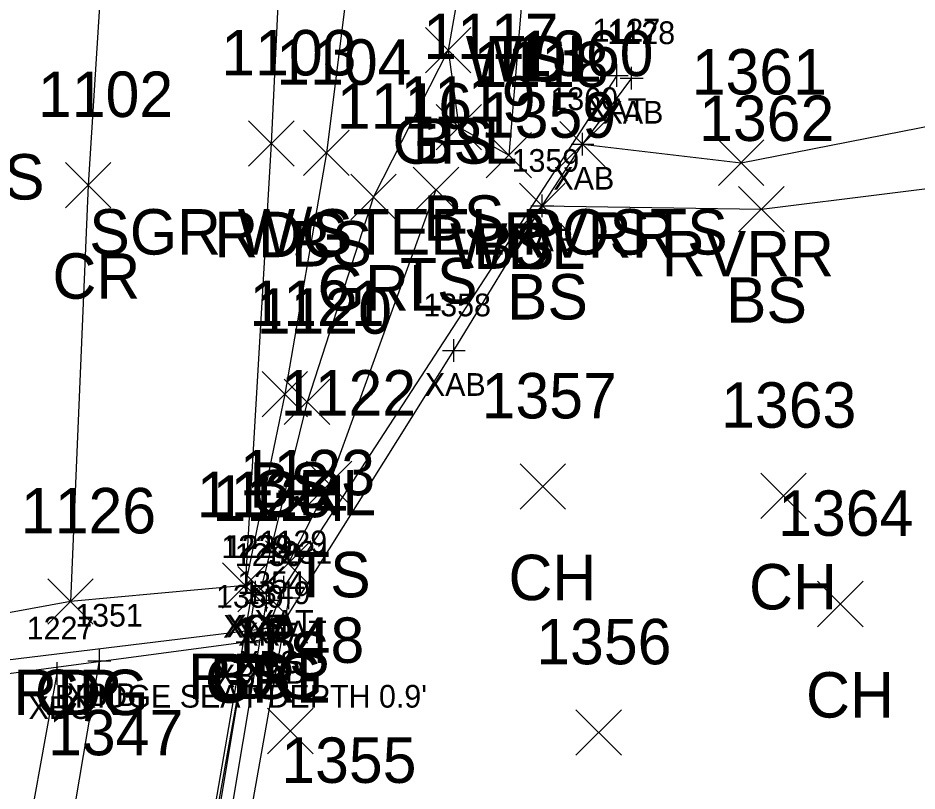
# Model space of a CAD drawing. Extents: x 1678553 to 1680768, y 787260 to 792325.
# Drawn here: x 1678697.83 to 1678737.39, y 787554.21 to 787588.24 of the extents above; entities that cross this region are included whole.
import ezdxf

# ---------------------------------------------------------------- set-up
doc = ezdxf.new("R2010")
doc.units = 0
for name, color, linetype in [('B_A', 7, 'Continuous'), ('B_C', 7, 'Continuous'), ('B_I', 7, 'Continuous'), ('B_TIC', 7, 'Continuous'), ('BB', 7, 'Continuous'), ('BDC', 7, 'Continuous'), ('BELB', 7, 'Continuous'), ('BF', 7, 'Continuous'), ('BR', 7, 'Continuous'), ('BSE', 7, 'Continuous'), ('BSUBM', 7, 'Continuous'), ('Default', 7, 'Continuous'), ('L_A', 7, 'Continuous'), ('L_I', 7, 'Continuous'), ('L_TIC', 7, 'Continuous'), ('LAWA', 7, 'Continuous'), ('LAWE', 7, 'Continuous'), ('LELB', 7, 'Continuous'), ('P_A', 7, 'Continuous'), ('P_I', 7, 'Continuous'), ('P_TIC', 7, 'Continuous'), ('PEU', 7, 'Continuous'), ('PRC', 7, 'Continuous'), ('R_A', 7, 'Continuous'), ('R_C', 7, 'Continuous'), ('R_I', 7, 'Continuous'), ('R_TIC', 7, 'Continuous'), ('RGR', 7, 'Continuous')]:
    doc.layers.add(name, color=color, linetype=linetype)

msp = doc.modelspace()

# ---------------------------------------------------------------- linework, layer by layer
at = {"layer": 'B_TIC'}
for p, q in [((1678724.175, 787585.703), (1678724.251, 787585.703)), ((1678724.834, 787585.589), (1678724.909, 787585.589)), ((1678722.672, 787582.686), (1678722.748, 787582.686)), ((1678722.672, 787582.686), (1678722.748, 787582.686)), ((1678720.903, 787579.967), (1678720.978, 787579.967)), ((1678717.015, 787573.607), (1678717.09, 787573.607)), ((1678709.532, 787563.18), (1678709.608, 787563.18)), ((1678708.126, 787562.968), (1678708.201, 787562.968)), ((1678708.286, 787562.971), (1678708.361, 787562.971)), ((1678708.763, 787562.617), (1678708.839, 787562.617)), ((1678709.747, 787562.716), (1678709.822, 787562.716)), ((1678708.828, 787561.383), (1678708.903, 787561.383)), ((1678709.077, 787560.939), (1678709.152, 787560.939)), ((1678707.935, 787560.782), (1678708.011, 787560.782)), ((1678701.415, 787559.95), (1678701.49, 787559.95)), ((1678699.566, 787559.385), (1678699.641, 787559.385))]:
    msp.add_line(p, q, dxfattribs=at)
for points in [[(1678724.172, 787585.203), (1678724.172, 787586.203)], [(1678724.83, 787585.089), (1678724.83, 787586.089)], [(1678723.672, 787585.703), (1678724.672, 787585.703)], [(1678724.33, 787585.589), (1678725.33, 787585.589)], [(1678722.669, 787582.186), (1678722.669, 787583.186)], [(1678722.669, 787582.186), (1678722.669, 787583.186)], [(1678722.169, 787582.686), (1678723.169, 787582.686)], [(1678722.169, 787582.686), (1678723.169, 787582.686)], [(1678720.9, 787579.467), (1678720.9, 787580.467)], [(1678720.4, 787579.967), (1678721.4, 787579.967)], [(1678717.011, 787573.107), (1678717.011, 787574.107)], [(1678716.511, 787573.607), (1678717.511, 787573.607)], [(1678709.529, 787562.68), (1678709.529, 787563.68)], [(1678708.123, 787562.468), (1678708.123, 787563.468)], [(1678708.282, 787562.471), (1678708.282, 787563.471)], [(1678709.029, 787563.18), (1678710.029, 787563.18)], [(1678709.743, 787562.216), (1678709.743, 787563.216)], [(1678707.623, 787562.968), (1678708.623, 787562.968)], [(1678707.782, 787562.971), (1678708.782, 787562.971)], [(1678708.76, 787562.117), (1678708.76, 787563.117)], [(1678708.26, 787562.617), (1678709.26, 787562.617)], [(1678709.243, 787562.716), (1678710.243, 787562.716)], [(1678708.824, 787560.883), (1678708.824, 787561.883)], [(1678707.932, 787560.282), (1678707.932, 787561.282)], [(1678708.324, 787561.383), (1678709.324, 787561.383)], [(1678709.073, 787560.439), (1678709.073, 787561.439)], [(1678708.573, 787560.939), (1678709.573, 787560.939)], [(1678701.411, 787559.45), (1678701.411, 787560.45)], [(1678707.432, 787560.782), (1678708.432, 787560.782)], [(1678699.562, 787558.885), (1678699.562, 787559.885)], [(1678700.911, 787559.95), (1678701.911, 787559.95)], [(1678699.062, 787559.385), (1678700.062, 787559.385)]]:
    msp.add_lwpolyline(points, dxfattribs=at)
at = {"layer": 'BB'}
for points in [[(1678701.803, 787526.419), (1678707.932, 787560.782)], [(1678695.571, 787525.394), (1678701.411, 787559.95)]]:
    msp.add_lwpolyline(points, dxfattribs=at)
at = {"layer": 'BDC'}
for points in [[(1678708.123, 787562.968), (1678704.887, 787544.249), (1678701.43, 787523.472)], [(1678708.282, 787562.971), (1678705.145, 787544.189), (1678701.582, 787523.722)]]:
    msp.add_lwpolyline(points, dxfattribs=at)
at = {"layer": 'BELB'}
msp.add_lwpolyline([(1678692.969, 787524.163), (1678696.171, 787540.725), (1678699.562, 787559.385)], dxfattribs=at)
at = {"layer": 'BF'}
msp.add_lwpolyline([(1678709.743, 787562.716), (1678706.422, 787543.978), (1678702.806, 787523.371)], dxfattribs=at)
at = {"layer": 'BR'}
msp.add_lwpolyline([(1678708.76, 787562.617), (1678705.642, 787543.945), (1678702.196, 787523.942)], dxfattribs=at)
at = {"layer": 'BSE'}
msp.add_lwpolyline([(1678689.043, 787558.968), (1678708.824, 787561.383)], dxfattribs=at)
at = {"layer": 'BSUBM'}
for points in [[(1678724.172, 787585.703), (1678709.529, 787563.18)], [(1678724.83, 787585.589), (1678722.669, 787582.686)], [(1678677.396, 787568.583), (1678684.574, 787562.134), (1678686.585, 787560.22), (1678689.048, 787558.274), (1678709.073, 787560.939), (1678717.011, 787573.607), (1678720.9, 787579.967), (1678722.669, 787582.686)]]:
    msp.add_lwpolyline(points, dxfattribs=at)
at = {"layer": 'Default'}
msp.add_line((1678709.529, 787563.18), (1678708.824, 787561.383), dxfattribs=at)
at = {"layer": 'L_TIC'}
for points in [[(1678715.762, 787585.825), (1678717.762, 787587.825)], [(1678717.762, 787585.825), (1678715.762, 787587.825)], [(1678716.223, 787582.431), (1678718.223, 787584.431)], [(1678718.223, 787582.431), (1678716.223, 787584.431)], [(1678721.669, 787581.686), (1678723.669, 787583.686)], [(1678723.669, 787581.686), (1678721.669, 787583.686)], [(1678710.399, 787581.3), (1678712.399, 787583.3)], [(1678712.399, 787581.3), (1678710.399, 787583.3)], [(1678718.428, 787581.197), (1678720.428, 787583.197)], [(1678720.428, 787581.197), (1678718.428, 787583.197)], [(1678718.428, 787581.197), (1678720.428, 787583.197)], [(1678720.428, 787581.197), (1678718.428, 787583.197)], [(1678728.644, 787580.87), (1678730.644, 787582.87)], [(1678730.644, 787580.87), (1678728.644, 787582.87)], [(1678715.221, 787579.674), (1678717.221, 787581.674)], [(1678717.221, 787579.674), (1678715.221, 787581.674)], [(1678719.9, 787578.967), (1678721.9, 787580.967)], [(1678721.9, 787578.967), (1678719.9, 787580.967)], [(1678729.536, 787578.825), (1678731.536, 787580.825)], [(1678731.536, 787578.825), (1678729.536, 787580.825)], [(1678708.575, 787570.681), (1678710.575, 787572.681)], [(1678710.575, 787570.681), (1678708.575, 787572.681)], [(1678710.522, 787566.739), (1678712.522, 787568.739)], [(1678712.522, 787566.739), (1678710.522, 787568.739)], [(1678719.923, 787566.613), (1678721.923, 787568.613)], [(1678721.923, 787566.613), (1678719.923, 787568.613)], [(1678730.507, 787566.204), (1678732.507, 787568.204)], [(1678732.507, 787566.204), (1678730.507, 787568.204)], [(1678708.718, 787563.23), (1678710.718, 787565.23)], [(1678710.718, 787563.23), (1678708.718, 787565.23)], [(1678706.824, 787562.264), (1678708.824, 787564.264)], [(1678708.824, 787562.264), (1678706.824, 787564.264)], [(1678733.014, 787561.445), (1678735.014, 787563.445)], [(1678735.014, 787561.445), (1678733.014, 787563.445)], [(1678708.811, 787555.853), (1678710.811, 787557.853)], [(1678710.811, 787555.853), (1678708.811, 787557.853)], [(1678722.379, 787555.79), (1678724.379, 787557.79)], [(1678724.379, 787555.79), (1678722.379, 787557.79)]]:
    msp.add_lwpolyline(points, dxfattribs=at)
at = {"layer": 'LAWA'}
msp.add_lwpolyline([(1678789.656, 787618.552), (1678782.283, 787633.906), (1678770.992, 787633.612), (1678749.841, 787630.92), (1678727.879, 787628.093), (1678728.529, 787616.427), (1678733.151, 787607.215), (1678734.093, 787597.695), (1678727.587, 787595.659), (1678724.828, 787595.572), (1678720.116, 787590.439), (1678719.428, 787582.197)], dxfattribs=at)
at = {"layer": 'LAWE'}
msp.add_lwpolyline([(1678722.669, 787582.686), (1678729.644, 787581.87), (1678749.304, 787585.723), (1678767.552, 787590.14), (1678784.526, 787599.947), (1678818.403, 787617.013)], dxfattribs=at)
at = {"layer": 'LELB'}
for points in [[(1678715.765, 787621.905), (1678715.125, 787612.098), (1678711.399, 787582.3), (1678709.575, 787571.681), (1678707.824, 787563.264)], [(1678720.9, 787579.967), (1678730.536, 787579.825), (1678747.484, 787581.937), (1678769.156, 787589.574), (1678788.925, 787598.347), (1678821.688, 787613.869)], [(1678727.587, 787595.659), (1678723.009, 787609.269), (1678719.987, 787605.203), (1678716.762, 787586.825), (1678717.223, 787583.431), (1678719.428, 787582.197)], [(1678716.221, 787580.674), (1678711.522, 787567.739), (1678709.718, 787564.23)]]:
    msp.add_lwpolyline(points, dxfattribs=at)
at = {"layer": 'P_TIC'}
for points in [[(1678707.977, 787581.71), (1678709.977, 787583.71)], [(1678709.977, 787581.71), (1678707.977, 787583.71)], [(1678699.915, 787579.881), (1678701.915, 787581.881)], [(1678701.915, 787579.881), (1678699.915, 787581.881)], [(1678706.824, 787562.264), (1678708.824, 787564.264)], [(1678708.824, 787562.264), (1678706.824, 787564.264)], [(1678699.138, 787561.553), (1678701.138, 787563.553)], [(1678701.138, 787561.553), (1678699.138, 787563.553)], [(1678699.138, 787561.553), (1678701.138, 787563.553)], [(1678701.138, 787561.553), (1678699.138, 787563.553)]]:
    msp.add_lwpolyline(points, dxfattribs=at)
at = {"layer": 'PEU'}
msp.add_lwpolyline([(1678707.071, 787835.603), (1678708.867, 787801.612), (1678711.158, 787769.032), (1678713.635, 787732.076), (1678713.931, 787704.33), (1678716.279, 787671.407), (1678712.683, 787651.273), (1678711.57, 787636.622), (1678710.351, 787611.373), (1678708.977, 787582.71), (1678707.824, 787563.264), (1678700.138, 787562.553), (1678691.169, 787560.916)], dxfattribs=at)
at = {"layer": 'PRC'}
msp.add_lwpolyline([(1678698.822, 787835.522), (1678700.146, 787799.389), (1678701.734, 787769.285), (1678704.119, 787733.19), (1678705.318, 787702.806), (1678705.892, 787671.867), (1678706.035, 787650.603), (1678702.844, 787611.285), (1678700.915, 787580.881), (1678700.138, 787562.553)], dxfattribs=at)
at = {"layer": 'R_TIC'}
for points in [[(1678715.762, 787585.825), (1678717.762, 787587.825)], [(1678717.762, 787585.825), (1678715.762, 787587.825)], [(1678712.474, 787579.36), (1678714.474, 787581.36)], [(1678714.474, 787579.36), (1678712.474, 787581.36)], [(1678709.548, 787570.341), (1678711.548, 787572.341)], [(1678711.548, 787570.341), (1678709.548, 787572.341)], [(1678707.51, 787562.102), (1678709.51, 787564.102)], [(1678709.51, 787562.102), (1678707.51, 787564.102)]]:
    msp.add_lwpolyline(points, dxfattribs=at)
at = {"layer": 'RGR'}
msp.add_lwpolyline([(1678716.762, 787586.825), (1678713.474, 787580.36), (1678710.548, 787571.341), (1678708.51, 787563.102)], dxfattribs=at)

# ---------------------------------------------------------------- texts
at = {"layer": 'B_A'}
for s, p in [('XAT', (1678722.876, 787583.703)), ('XAB', (1678723.551, 787583.589)), ('XAB', (1678721.389, 787580.686)), ('XAB', (1678721.389, 787580.686)), ('XAB', (1678719.62, 787577.967)), ('XAB', (1678715.732, 787571.607)), ('XAT', (1678708.234, 787561.18)), ('XCB', (1678706.859, 787560.968)), ('XCT', (1678707.003, 787560.971)), ('XRF', (1678707.52, 787560.617)), ('XFAT', (1678707.999, 787560.716)), ('XBS', (1678707.564, 787559.383)), ('XBIB', (1678706.503, 787558.782)), ('XAB', (1678707.794, 787558.939)), ('XBIB', (1678699.982, 787557.95)), ('XBC', (1678698.299, 787557.385))]:
    msp.add_text(s, height=1, dxfattribs=at).set_placement(p)
at = {"layer": 'B_C'}
msp.add_text("BRIDGE SEAT DEPTH 0.9'", height=1, dxfattribs=at).set_placement((1678699.447, 787557.883))
at = {"layer": 'B_I'}
for s, p in [('1127', (1678723.109, 787587.203)), ('1128', (1678723.768, 787587.089)), ('1360', (1678721.255, 787584.186)), ('1360', (1678721.255, 787584.186)), ('1359', (1678719.549, 787581.467)), ('1358', (1678715.665, 787575.107)), ('1129', (1678708.462, 787564.68)), ('1228', (1678706.776, 787564.468)), ('1229', (1678706.932, 787564.471)), ('1231', (1678708.68, 787564.216)), ('1230', (1678707.37, 787564.117)), ('1354', (1678707.478, 787562.883)), ('1350', (1678706.542, 787562.282)), ('1349', (1678707.723, 787562.439)), ('1351', (1678700.348, 787561.45)), ('1227', (1678698.216, 787560.885))]:
    msp.add_text(s, height=1, dxfattribs=at).set_placement(p)
at = {"layer": 'L_A'}
for s, p in [('WDL', (1678717.533, 787585.439)), ('TS', (1678718.525, 787585.439)), ('BS', (1678715.203, 787581.825)), ('BS', (1678715.664, 787578.431)), ('RVRR', (1678719.181, 787577.686)), ('BS', (1678709.84, 787577.3)), ('WDL', (1678716.846, 787577.197)), ('BS', (1678717.869, 787577.197)), ('RVRR', (1678726.155, 787576.87)), ('TS', (1678714.63, 787575.674)), ('BS', (1678719.34, 787574.967)), ('BS', (1678728.977, 787574.825)), ('BS', (1678708.016, 787566.681)), ('TS', (1678709.932, 787562.739)), ('CH', (1678719.411, 787562.613)), ('CH', (1678729.995, 787562.204)), ('TS', (1678708.127, 787559.23)), ('BS', (1678706.265, 787558.264)), ('CH', (1678732.502, 787557.445))]:
    msp.add_text(s, height=2, dxfattribs=at).set_placement(p)
at = {"layer": 'L_I'}
for s, p in [('1117', (1678715.664, 787586.431)), ('1360', (1678719.842, 787585.686)), ('1104', (1678709.195, 787585.3)), ('1118', (1678717.87, 787585.197)), ('1118', (1678717.87, 787585.197)), ('1361', (1678727.471, 787584.87)), ('1119', (1678714.654, 787583.674)), ('1359', (1678718.199, 787582.967)), ('1362', (1678727.796, 787582.825)), ('1121', (1678708.016, 787574.681)), ('1122', (1678709.397, 787570.739)), ('1357', (1678718.23, 787570.613)), ('1363', (1678728.767, 787570.204)), ('1123', (1678707.592, 787567.23)), ('1125', (1678705.698, 787566.264)), ('1364', (1678731.274, 787565.445)), ('1348', (1678707.118, 787559.853)), ('1356', (1678720.632, 787559.79)), ('1347', (1678699.153, 787555.786)), ('1355', (1678709.414, 787554.571))]:
    msp.add_text(s, height=2, dxfattribs=at).set_placement(p)
at = {"layer": 'P_A'}
for s, p in [('RDG', (1678706.465, 787577.71)), ('CR', (1678699.348, 787575.881)), ('RDG', (1678705.312, 787558.264)), ('RDG', (1678697.627, 787557.553)), ('CR', (1678698.571, 787557.553))]:
    msp.add_text(s, height=2, dxfattribs=at).set_placement(p)
at = {"layer": 'P_I'}
for s, p in [('1103', (1678706.773, 787585.71)), ('1102', (1678698.71, 787583.881)), ('1125', (1678705.698, 787566.264)), ('1126', (1678697.958, 787565.553)), ('1126', (1678697.958, 787565.553))]:
    msp.add_text(s, height=2, dxfattribs=at).set_placement(p)
at = {"layer": 'R_A'}
for p in [(1678714.305, 787581.825), (1678711.017, 787575.36), (1678708.091, 787566.341), (1678706.054, 787558.102)]:
    msp.add_text('GRL', height=2, dxfattribs=at).set_placement(p)
at = {"layer": 'R_C'}
for p in [(1678670.915, 787580.248), (1678700.967, 787577.825)]:
    msp.add_text('SGR W/STEEL POSTS', height=2, dxfattribs=at).set_placement(p)
at = {"layer": 'R_I'}
for s, p in [('1116', (1678711.86, 787583.36)), ('1120', (1678708.335, 787574.341)), ('1124', (1678706.385, 787566.102))]:
    msp.add_text(s, height=2, dxfattribs=at).set_placement(p)

doc.saveas('drawing.dxf')
